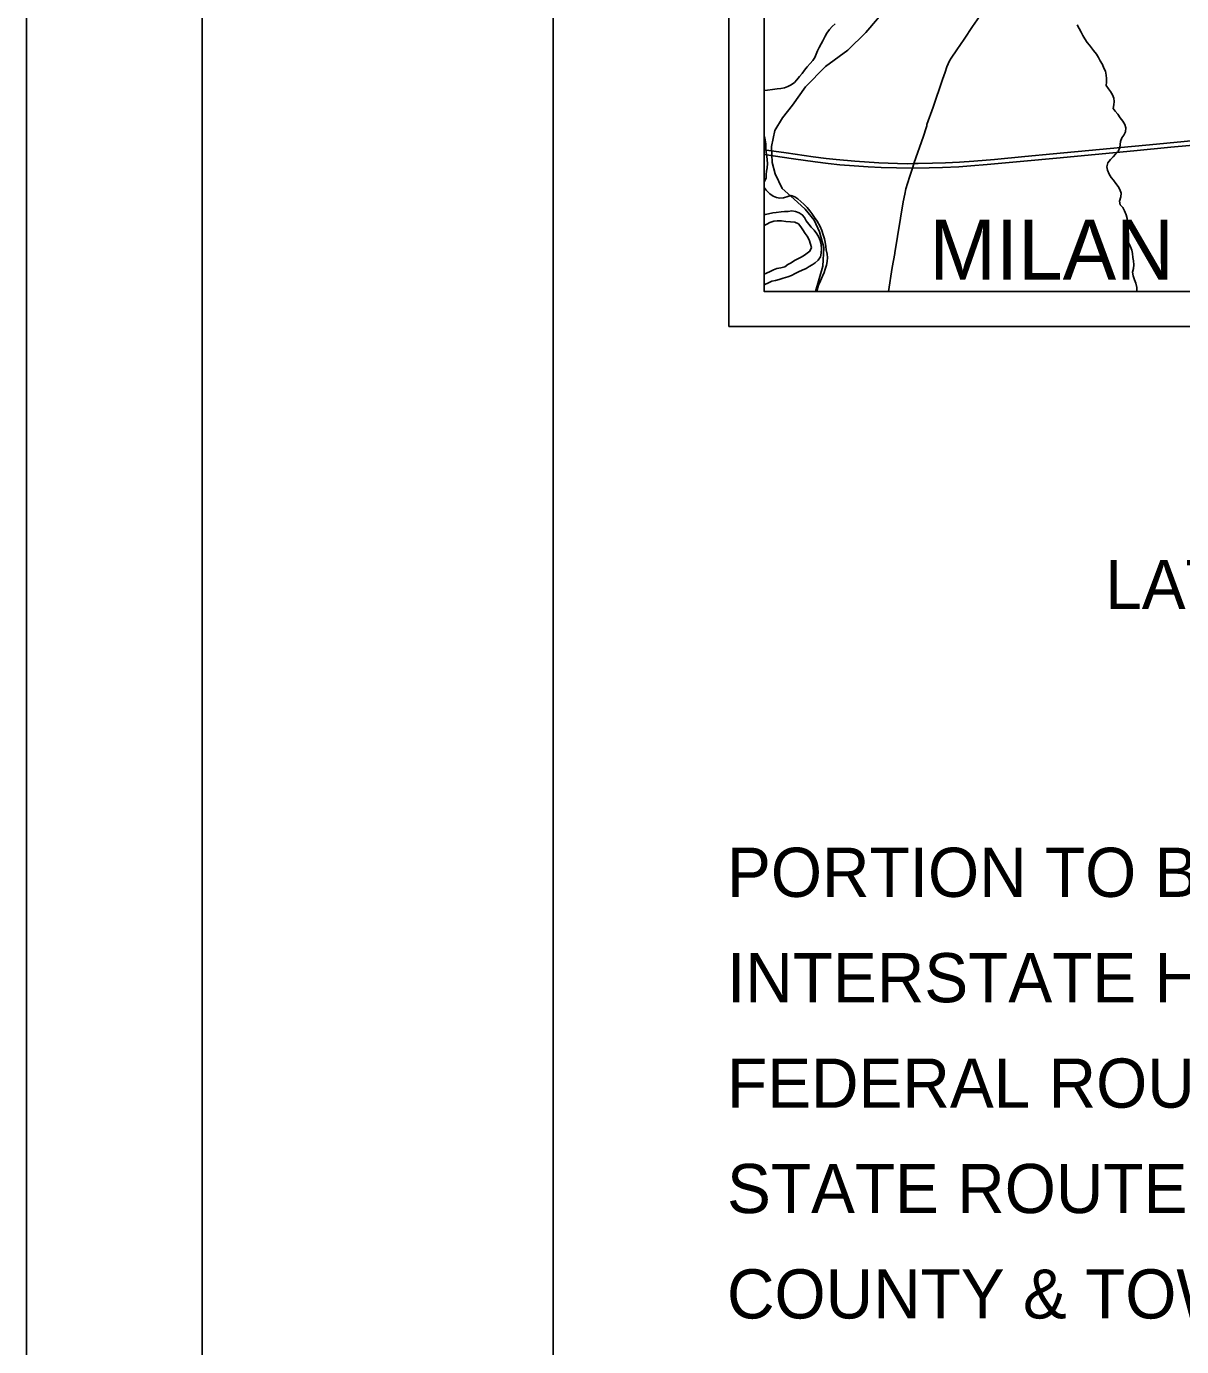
# Model space of a CAD drawing. Extents: x 0 to 34, y 0 to 22.
# Drawn here: x 0 to 3.288, y 11.097 to 14.854 of the extents above; entities that cross this region are included whole.
import ezdxf

# ---------------------------------------------------------------- set-up
doc = ezdxf.new("R2010")
doc.units = 0
for name, color, linetype in [('GM_X_Corporation', 7, 'Continuous'), ('GM_X_Interstate_Route', 7, 'Continuous'), ('GM_X_Major_River', 7, 'Continuous'), ('GM_X_Minor_River', 7, 'Continuous'), ('GM_X_Rail_Line', 7, 'Continuous'), ('GM_X_Township_Road', 7, 'Continuous'), ('GM_X_Township_Text', 7, 'Continuous'), ('SH_Border', 7, 'Continuous'), ('SH_Cut_Line', 7, 'Continuous'), ('SH_Data', 7, 'Continuous'), ('SH_Text', 7, 'Continuous')]:
    doc.layers.add(name, color=color, linetype=linetype)

msp = doc.modelspace()

# ---------------------------------------------------------------- linework, layer by layer
at = {"layer": 'GM_X_Corporation'}
for points in [[(2.1, 20.7089), (2.1, 14.1), (8.9, 14.1), (8.9, 18.9067)], [(2.1, 16.8894), (2.1, 14.1), (4.4374, 14.1), (4.437, 14.154), (4.4348, 14.2876), (4.4332, 14.3373), (4.4327, 14.3684), (4.4325, 14.3733), (4.4317, 14.396), (4.4315, 14.4227), (4.4318, 14.4347), (4.431, 14.4741), (4.4301, 14.5114), (4.4285, 14.5905), (4.4282, 14.5944), (4.4282, 14.6082), (4.4279, 14.6184), (4.4276, 14.6307), (4.4274, 14.64), (4.4269, 14.6591), (4.427, 14.6635), (4.4253, 14.7443), (4.4234, 14.8562)]]:
    msp.add_lwpolyline(points, dxfattribs=at)
at = {"layer": 'GM_X_Interstate_Route'}
for points in [[(2.1, 14.5035), (2.1139, 14.5016), (2.163, 14.4944), (2.2398, 14.4832), (2.2768, 14.4784), (2.3048, 14.4755), (2.3583, 14.4706), (2.427, 14.4661), (2.4798, 14.4644), (2.5076, 14.4636), (2.5267, 14.4638), (2.5387, 14.464), (2.5791, 14.4647), (2.6164, 14.466), (2.6567, 14.468), (2.6971, 14.4708), (2.7559, 14.4757), (2.8425, 14.4843), (2.923, 14.4918), (3.217, 14.5193), (3.4336, 14.5396)], [(2.1, 14.4899), (2.1835, 14.4775), (2.245, 14.4689), (2.282, 14.4643), (2.316, 14.4608), (2.3562, 14.4574), (2.3965, 14.4546), (2.4337, 14.4529), (2.4772, 14.4516), (2.5224, 14.4511), (2.5237, 14.4511), (2.5703, 14.4516), (2.6075, 14.4528), (2.654, 14.4551), (2.6881, 14.4573), (2.7346, 14.4612), (2.8398, 14.4711), (2.9326, 14.4795), (3.1524, 14.5001), (3.2576, 14.5102), (3.3535, 14.5193)]]:
    msp.add_lwpolyline(points, dxfattribs=at)
at = {"layer": 'GM_X_Major_River'}
for points in [[(2.302, 14.8619), (2.294, 14.8538), (2.2861, 14.8458), (2.2782, 14.8355), (2.2737, 14.8267), (2.267, 14.8137), (2.2625, 14.805), (2.2572, 14.7947), (2.2523, 14.7847), (2.2482, 14.7752), (2.2445, 14.7657), (2.2392, 14.7569), (2.2309, 14.7485), (2.2223, 14.7389), (2.2151, 14.7301), (2.208, 14.7206), (2.2004, 14.7114), (2.1933, 14.7026), (2.1865, 14.695), (2.1774, 14.6885), (2.1676, 14.6831), (2.1585, 14.6796), (2.1475, 14.678), (2.1372, 14.6768), (2.1236, 14.6748), (2.1099, 14.6732), (2.1004, 14.672), (2.1, 14.6719)], [(2.1, 14.4128), (2.1011, 14.4131), (2.1055, 14.423), (2.1055, 14.4325), (2.1073, 14.442), (2.1088, 14.4516), (2.1094, 14.4645), (2.1086, 14.4744), (2.1074, 14.485), (2.1062, 14.4953), (2.1053, 14.5082), (2.1045, 14.5203), (2.1017, 14.5359), (2.1, 14.5415)], [(2.1, 14.1193), (2.1023, 14.12), (2.1122, 14.1243), (2.122, 14.1289), (2.1326, 14.1316), (2.1429, 14.134), (2.1546, 14.1378), (2.1675, 14.1413), (2.1777, 14.1452), (2.188, 14.1506), (2.1982, 14.1556), (2.2088, 14.161), (2.2194, 14.1656), (2.2281, 14.1706), (2.2368, 14.176), (2.2451, 14.181), (2.2542, 14.189), (2.2602, 14.1986), (2.2624, 14.2085), (2.2634, 14.2225), (2.2626, 14.2328), (2.2595, 14.2449), (2.256, 14.2544), (2.2502, 14.2639), (2.2426, 14.2741), (2.2342, 14.2832), (2.2273, 14.2915), (2.22, 14.301), (2.2154, 14.3101), (2.2085, 14.3184), (2.1997, 14.3236), (2.1894, 14.3274), (2.1791, 14.3292), (2.1689, 14.328), (2.1579, 14.3279), (2.1484, 14.3267), (2.1343, 14.3251), (2.1245, 14.3235), (2.1127, 14.3212), (2.1032, 14.3192), (2.1, 14.3184)], [(2.1, 14.288), (2.108, 14.2919), (2.1167, 14.2961), (2.1277, 14.2996), (2.1372, 14.3008), (2.1493, 14.3005), (2.1615, 14.2994), (2.1748, 14.298), (2.1877, 14.2973), (2.1976, 14.2925), (2.2041, 14.2838), (2.2099, 14.275), (2.2168, 14.2652), (2.2229, 14.2573), (2.2279, 14.2466), (2.2322, 14.2349), (2.2349, 14.2246), (2.2304, 14.2144), (2.2149, 14.2032), (2.2051, 14.1975), (2.1964, 14.1925), (2.1866, 14.1878), (2.1771, 14.1817), (2.168, 14.1767), (2.1586, 14.1702), (2.1476, 14.1674), (2.1366, 14.1651), (2.1271, 14.1612), (2.1169, 14.157), (2.1067, 14.152), (2.1, 14.1491)]]:
    msp.add_lwpolyline(points, dxfattribs=at)
at = {"layer": 'GM_X_Minor_River'}
for points in [[(2.9915, 14.859), (2.9965, 14.8488), (3.0023, 14.8382), (3.0076, 14.8287), (3.013, 14.8189), (3.0196, 14.8083), (3.0261, 14.8007), (3.0322, 14.7931), (3.0379, 14.7856), (3.0464, 14.7757), (3.0521, 14.7659), (3.0571, 14.7564), (3.0629, 14.7462), (3.0675, 14.7359), (3.0718, 14.7265), (3.0738, 14.7155), (3.0746, 14.706), (3.0747, 14.6957), (3.074, 14.6858), (3.0805, 14.6771), (3.0862, 14.6688), (3.092, 14.6597), (3.0955, 14.6498), (3.0967, 14.6403), (3.0952, 14.6308), (3.0938, 14.6209), (3.0995, 14.613), (3.1068, 14.605), (3.1133, 14.5944), (3.1214, 14.585), (3.1268, 14.5747), (3.1295, 14.5656), (3.1288, 14.5546), (3.1239, 14.5451), (3.1183, 14.5374)], [(3.1183, 14.5374), (3.1146, 14.5268), (3.1128, 14.51), (3.1079, 14.4982), (3.1008, 14.4906), (3.0936, 14.4829), (3.0857, 14.476), (3.0785, 14.4661), (3.0759, 14.4547), (3.0779, 14.4452), (3.0825, 14.4338), (3.0883, 14.4243), (3.0948, 14.4164), (3.1013, 14.4069), (3.1075, 14.3986), (3.1129, 14.3903), (3.1163, 14.3797), (3.1157, 14.369), (3.1119, 14.3572), (3.1132, 14.3466), (3.1216, 14.339), (3.1262, 14.3292), (3.1304, 14.3182), (3.1332, 14.3075), (3.1329, 14.295), (3.1314, 14.2851), (3.1304, 14.2741), (3.1297, 14.2645), (3.1286, 14.255), (3.1336, 14.2459), (3.1394, 14.2357), (3.1432, 14.2266), (3.1467, 14.2175), (3.1483, 14.208), (3.1499, 14.1966), (3.1511, 14.1871), (3.1523, 14.1761), (3.1516, 14.1655), (3.1483, 14.1552), (3.1506, 14.1445), (3.1545, 14.1328), (3.1584, 14.1233), (3.1611, 14.1108), (3.1612, 14.1)], [(2.1, 14.3954), (2.1058, 14.388), (2.1161, 14.3782), (2.1257, 14.3714), (2.1352, 14.3677), (2.1447, 14.3659), (2.1557, 14.3663), (2.1674, 14.3706), (2.1773, 14.3729), (2.1876, 14.3692), (2.1956, 14.3639), (2.2044, 14.356), (2.2132, 14.3481), (2.2228, 14.339), (2.23, 14.3299), (2.2362, 14.3216), (2.2438, 14.3106), (2.2507, 14.3004), (2.26, 14.2845), (2.2642, 14.2739), (2.2685, 14.2614), (2.2716, 14.2496), (2.274, 14.2401), (2.2759, 14.2283), (2.2771, 14.2181), (2.2791, 14.2063), (2.2803, 14.1964), (2.28, 14.185), (2.2778, 14.1747), (2.2741, 14.1633), (2.2708, 14.1538), (2.2659, 14.1435), (2.2603, 14.1298), (2.255, 14.1183), (2.251, 14.105), (2.2499, 14.1)]]:
    msp.add_lwpolyline(points, dxfattribs=at)
at = {"layer": 'GM_X_Rail_Line'}
msp.add_lwpolyline([(2.2464, 14.1), (2.2668, 14.1719), (2.2701, 14.2246), (2.2577, 14.2692), (2.243, 14.3024), (2.2171, 14.3346), (2.1851, 14.3637), (2.1516, 14.3933), (2.1319, 14.4344), (2.1227, 14.467), (2.1207, 14.5129), (2.1301, 14.5585), (2.1526, 14.5946), (2.1807, 14.6303), (2.2177, 14.682), (2.2745, 14.7402), (2.3385, 14.787), (2.3897, 14.8368), (2.4224, 14.8755), (2.4871, 14.9592), (2.5237, 14.9937), (2.567, 15.0258), (2.6022, 15.0634), (2.7297, 15.2056)], dxfattribs=at)
at = {"layer": 'GM_X_Township_Road'}
for points in [[(2.4722, 14.2101), (2.4963, 14.3553), (2.5003, 14.3767), (2.5037, 14.3919), (2.5079, 14.4069), (2.5144, 14.4277), (2.5224, 14.4511), (2.5264, 14.463), (2.5267, 14.4638), (2.5536, 14.5424), (2.5614, 14.5659), (2.5631, 14.5718), (2.5637, 14.5747), (2.5811, 14.6243), (2.6083, 14.7036), (2.6152, 14.7243), (2.6206, 14.7389), (2.6242, 14.7475), (2.6282, 14.756), (2.6329, 14.7641), (2.6482, 14.7876), (2.6692, 14.8185), (2.6937, 14.8544), (2.7128, 14.8827)], [(2.4545, 14.1), (2.4649, 14.1684), (2.4719, 14.2081), (2.4722, 14.2101)]]:
    msp.add_lwpolyline(points, dxfattribs=at)
at = {"layer": 'SH_Border'}
for points in [[(0.5, 21.5), (1.5, 21.5), (1.5, 0.5), (0.5, 0.5)], [(1.5, 21.5), (33.5, 21.5), (33.5, 0.5), (1.5, 0.5)]]:
    msp.add_lwpolyline(points, close=True, dxfattribs=at)
at = {"layer": 'SH_Cut_Line'}
msp.add_lwpolyline([(0, 0), (34, 0), (34, 22), (0, 22)], close=True, dxfattribs=at)
at = {"layer": 'SH_Data'}
for p, q in [((2, 21), (2, 14)), ((2.1, 20.9), (2.1, 14.1)), ((2.1, 14.1), (8.9, 14.1)), ((2.1, 14.1), (2.1, 14.1)), ((2, 14), (9, 14))]:
    msp.add_line(p, q, dxfattribs=at)

# ---------------------------------------------------------------- texts
at = {"layer": 'GM_X_Township_Text'}
msp.add_text('MILAN', height=0.17045, rotation=0, dxfattribs=at).set_placement((2.5702, 14.1339))
at = {"layer": 'SH_Text'}
for s, p in [('LATITUDE:  41°22\'01"     LONGITUDE:  82°30\'43"', (3.071, 13.1959)), ('PORTION TO BE IMPROVED', (1.9944, 12.3767)), ('INTERSTATE HIGHWAY', (1.9944, 12.0767)), ('FEDERAL ROUTES', (1.9944, 11.7767)), ('STATE ROUTES', (1.9944, 11.4767)), ('COUNTY & TOWNSHIP ROADS', (1.9944, 11.1767))]:
    msp.add_text(s, height=0.14, dxfattribs=at).set_placement(p)

doc.saveas('drawing.dxf')
